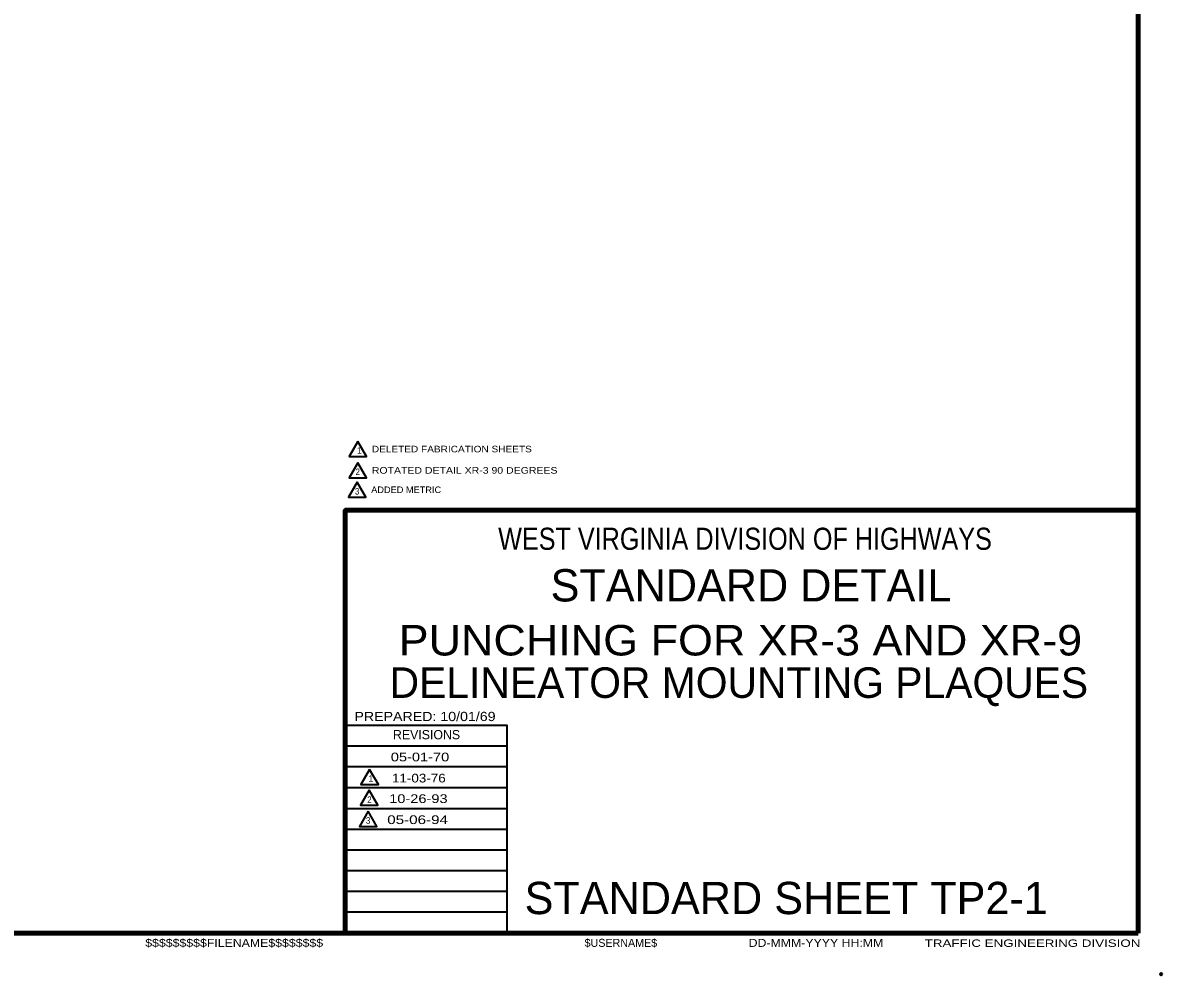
# Model space of a CAD drawing. Extents: x -74 to 639, y -412 to 42.
# Drawn here: x 377.5 to 638.5, y -411.7 to -193.4 of the extents above; entities that cross this region are included whole.
import ezdxf
from ezdxf.enums import TextEntityAlignment as Align

# ---------------------------------------------------------------- set-up
doc = ezdxf.new("R2010")
doc.units = 0
doc.header["$PDMODE"] = 32
doc.header["$PDSIZE"] = 0.5
doc.layers.add('1', color=7, linetype='Continuous', lineweight=40)
doc.layers.add('61', color=7, linetype='Continuous', lineweight=35)

msp = doc.modelspace()

# ---------------------------------------------------------------- linework, layer by layer
at = {"layer": '1', "lineweight": 158}
for q in [(633.015, 36.349), (633.015, -305.151), (-26.651, -402.068)]:
    msp.add_line((633.015, -402.068), q, dxfattribs=at)
at = {"layer": '1', "lineweight": 13}
msp.add_line((633.015, -402.068), (633.015, 36.349), dxfattribs=at)
at = {"layer": '1', "lineweight": 35}
for p, q in [((488.432, -359.234), (451.349, -359.234)), ((488.432, -363.984), (451.349, -363.984)), ((488.432, -368.818), (451.349, -368.818)), ((488.432, -373.568), (451.349, -373.568)), ((488.432, -378.318), (451.349, -378.318)), ((488.432, -383.068), (451.349, -383.068)), ((488.432, -387.818), (451.349, -387.818)), ((488.432, -392.568), (451.349, -392.568)), ((488.432, -397.318), (451.349, -397.318))]:
    msp.add_line(p, q, dxfattribs=at)
for points in [[(454.203, -289.382), (452.203, -292.846), (456.203, -292.846)], [(454.203, -294.266), (452.203, -297.73), (456.203, -297.73)], [(454.062, -298.716), (452.062, -302.18), (456.062, -302.18)], [(456.924, -364.594), (454.924, -368.058), (458.924, -368.058)], [(456.798, -369.291), (454.798, -372.755), (458.798, -372.755)], [(456.572, -374.167), (454.572, -377.631), (458.572, -377.631)]]:
    msp.add_lwpolyline(points, close=True, dxfattribs=at)
at = {"layer": '1', "lineweight": 158}
msp.add_lwpolyline([(451.349, -402.068), (451.349, -305.151), (633.015, -305.151)], dxfattribs=at)
at = {"layer": '1', "lineweight": 35}
msp.add_lwpolyline([(488.432, -402.068), (488.432, -354.484), (451.349, -354.484)], dxfattribs=at)
at = {"layer": '1'}
msp.add_point((638.265, -411.484), dxfattribs=at)
at = {"layer": '61', "lineweight": 53}
for q in [(505.765, -402.068), (505.765, -402.068), (505.765, -402.068), (506.015, -402.068), (506.015, -402.068)]:
    msp.add_line((633.015, -402.068), q, dxfattribs=at)

# ---------------------------------------------------------------- texts
at = {"layer": '1'}
for s, height, p in [('1', 1.5, (453.995, -292.228)), ('REVISIONS', 2.114, (462.265, -357.651)), ('1', 1.5, (456.651, -367.403)), ('STANDARD SHEET TP2-1 ', 7.401, (492.432, -397.734)), ('$USERNAME$', 1.833, (506.182, -405.234))]:
    msp.add_text(s, height=height, dxfattribs=at).set_placement(p)
for s, height, width, p in [('DELETED FABRICATION SHEETS', 1.5, 1.15, (457.427, -291.884)), ('2', 1.5, 0.9, (453.704, -297.111)), ('ROTATED DETAIL XR-3 90 DEGREES', 1.5, 1.2, (457.427, -296.768)), ('3', 1.5, 0.9, (453.563, -301.561)), ('ADDED METRIC', 1.5, 1.05, (457.285, -301.218)), ('PREPARED: 10/01/69', 2.114, 1.15, (453.432, -353.484)), ('2', 1.5, 0.9, (456.376, -372.249)), ('3', 1.5, 0.9, (456.074, -377.012)), ('$$$$$$$$$FILENAME$$$$$$$$', 1.833, 1.15, (405.515, -405.234)), ('DD-MMM-YYYY HH:MM', 1.833, 1.15, (543.765, -405.234)), ('TRAFFIC ENGINEERING DIVISION', 1.693, 1.35, (584.099, -405.234))]:
    msp.add_text(s, height=height, dxfattribs=dict(at, width=width)).set_placement(p)
for s, height, width, p in [('WEST VIRGINIA DIVISION OF HIGHWAYS', 5.074, 0.85, (542.932, -314.234)), ('PUNCHING FOR XR-3 AND XR-9', 6.993, 1.1, (541.871, -338.447)), ('05-01-70', 2, 1.25, (468.47, -362.714)), ('11-03-76', 2, 1.15, (468.199, -367.554)), ('10-26-93', 2, 1.25, (468.094, -372.268)), ('05-06-94', 2, 1.3, (467.913, -377.087))]:
    msp.add_text(s, height=height, dxfattribs=dict(at, width=width)).set_placement(p, align=Align.CENTER)
for s, height, p in [('STANDARD DETAIL', 7.401, (544.307, -326.068)), ('DELINEATOR MOUNTING PLAQUES', 6.993, (541.524, -348.168))]:
    msp.add_text(s, height=height, dxfattribs=at).set_placement(p, align=Align.CENTER)

doc.saveas('drawing.dxf')
